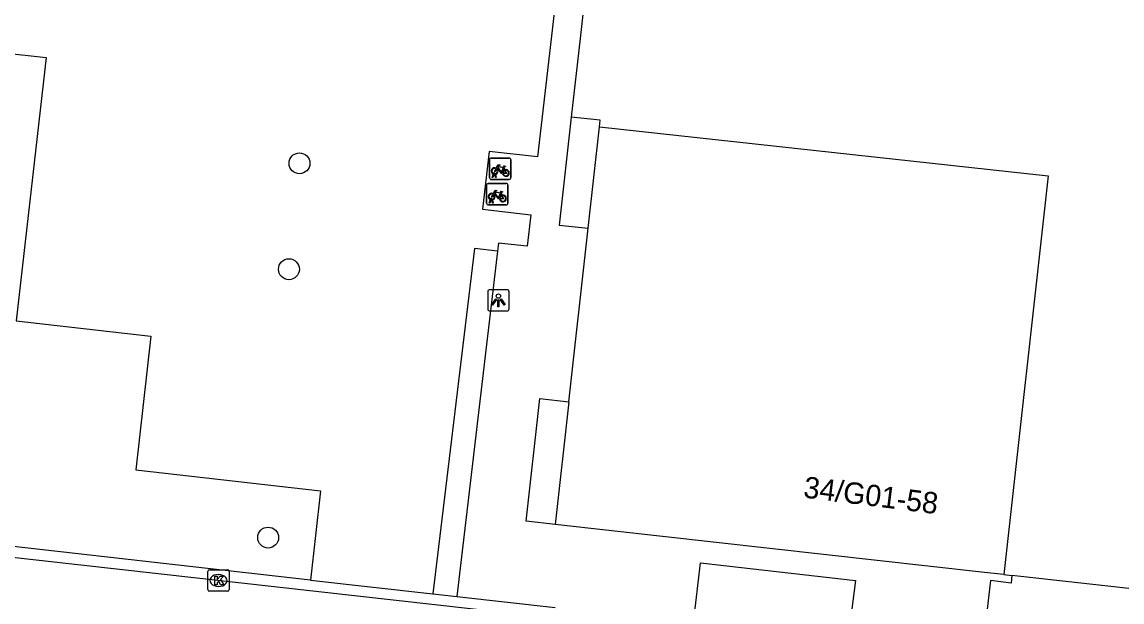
# Model space of a CAD drawing. Extents: x 161928 to 163055, y 386475 to 387428.
# Drawn here: x 162126.5 to 162177.9, y 387093.2 to 387120.3 of the extents above; entities that cross this region are included whole.
import ezdxf

# ---------------------------------------------------------------- set-up
doc = ezdxf.new("R2010")
doc.units = 0
for name, color, linetype in [('IMGEO_Boom', 7, 'Continuous'), ('IMGEO_Fietsenrek', 7, 'Continuous'), ('IMGEO_Groenvoorziening', 7, 'Continuous'), ('IMGEO_Kolk', 7, 'Continuous'), ('IMGEO_Lichtpunt', 7, 'Continuous'), ('IMGEO_Pand', 7, 'Continuous'), ('IMGEO_Pand_nummerreeks', 7, 'Continuous'), ('IMGEO_Rijbaan_lokaal_open', 7, 'Continuous'), ('IMGEO_Voetpad_open', 7, 'Continuous')]:
    doc.layers.add(name, color=color, linetype=linetype)

msp = doc.modelspace()

# ---------------------------------------------------------------- linework, layer by layer
at = {"layer": 'IMGEO_Boom'}
for centre in [(162139.439, 387113.732), (162138.945, 387108.775), (162137.971, 387096.215)]:
    msp.add_circle(centre, 0.489, dxfattribs=at)
at = {"layer": 'IMGEO_Fietsenrek'}
for p, q in [((162148.334, 387113.053), (162148.334, 387113.894)), ((162148.334, 387113.894), (162148.334, 387113.053)), ((162148.409, 387113.978), (162149.25, 387113.978)), ((162149.25, 387113.978), (162148.409, 387113.978)), ((162149.334, 387113.903), (162149.334, 387113.062)), ((162149.334, 387113.062), (162149.334, 387113.903)), ((162148.461, 387113.062), (162148.5, 387113.222)), ((162148.495, 387113.062), (162148.461, 387113.062)), ((162148.53, 387113.21), (162148.495, 387113.062)), ((162148.572, 387113.234), (162148.571, 387113.238)), ((162148.613, 387113.062), (162148.579, 387113.204)), ((162148.603, 387113.245), (162148.604, 387113.238)), ((162148.611, 387113.208), (162148.646, 387113.062)), ((162148.646, 387113.062), (162148.613, 387113.062)), ((162149.021, 387113.527), (162149.057, 387113.432)), ((162148.195, 387111.861), (162148.195, 387112.702)), ((162148.195, 387112.702), (162148.195, 387111.861)), ((162148.27, 387112.786), (162149.111, 387112.786)), ((162149.111, 387112.786), (162148.27, 387112.786)), ((162149.259, 387112.978), (162148.418, 387112.978)), ((162148.418, 387112.978), (162149.259, 387112.978)), ((162149.195, 387112.711), (162149.195, 387111.87)), ((162149.195, 387111.87), (162149.195, 387112.711)), ((162148.322, 387111.87), (162148.361, 387112.03)), ((162148.391, 387112.018), (162148.356, 387111.87)), ((162148.433, 387112.042), (162148.432, 387112.046)), ((162148.474, 387111.87), (162148.44, 387112.012)), ((162148.464, 387112.053), (162148.465, 387112.046)), ((162148.472, 387112.016), (162148.507, 387111.87)), ((162148.882, 387112.335), (162148.918, 387112.24)), ((162149.12, 387111.786), (162148.279, 387111.786)), ((162148.279, 387111.786), (162149.12, 387111.786)), ((162148.356, 387111.87), (162148.322, 387111.87)), ((162148.507, 387111.87), (162148.474, 387111.87))]:
    msp.add_line(p, q, dxfattribs=at)
for points in [[(162148.647, 387113.504), (162148.742, 387113.668), (162148.828, 387113.654), (162148.83, 387113.645), (162148.774, 387113.634), (162148.747, 387113.589), (162149.003, 387113.548)], [(162148.99, 387113.523), (162148.733, 387113.564), (162148.716, 387113.535), (162148.883, 387113.315), (162148.99, 387113.523)], [(162149.003, 387113.548), (162149.028, 387113.597), (162149.022, 387113.601), (162148.999, 387113.605), (162148.987, 387113.612), (162148.986, 387113.615), (162148.988, 387113.62), (162149.083, 387113.605), (162149.085, 387113.595), (162149.075, 387113.582), (162149.063, 387113.576), (162149.049, 387113.582), (162149.021, 387113.527)], [(162148.668, 387113.452), (162148.616, 387113.362), (162148.576, 387113.337), (162148.577, 387113.384), (162148.632, 387113.478)], [(162148.943, 387113.26), (162148.893, 387113.26), (162148.702, 387113.511), (162148.683, 387113.479)], [(162149.038, 387113.425), (162149.008, 387113.502), (162148.899, 387113.284), (162148.942, 387113.284)], [(162148.972, 387113.284), (162149.092, 387113.283), (162149.048, 387113.397)], [(162149.068, 387113.404), (162149.123, 387113.259), (162148.973, 387113.259)], [(162148.529, 387112.26), (162148.477, 387112.17), (162148.437, 387112.145), (162148.438, 387112.192), (162148.493, 387112.286)], [(162148.508, 387112.312), (162148.603, 387112.476), (162148.689, 387112.462), (162148.691, 387112.453), (162148.635, 387112.442), (162148.608, 387112.397), (162148.864, 387112.356)], [(162148.804, 387112.068), (162148.754, 387112.068), (162148.563, 387112.319), (162148.544, 387112.287)], [(162148.851, 387112.331), (162148.594, 387112.372), (162148.577, 387112.343), (162148.744, 387112.123), (162148.851, 387112.331)], [(162148.899, 387112.233), (162148.869, 387112.31), (162148.76, 387112.092), (162148.803, 387112.092)], [(162148.833, 387112.092), (162148.953, 387112.091), (162148.909, 387112.205)], [(162148.929, 387112.212), (162148.984, 387112.067), (162148.834, 387112.067)], [(162148.864, 387112.356), (162148.889, 387112.405), (162148.883, 387112.409), (162148.86, 387112.413), (162148.848, 387112.42), (162148.847, 387112.423), (162148.849, 387112.428), (162148.944, 387112.413), (162148.946, 387112.403), (162148.936, 387112.39), (162148.924, 387112.384), (162148.91, 387112.39), (162148.882, 387112.335)]]:
    msp.add_lwpolyline(points, dxfattribs=at)
for centre, radius, start, end in [((162148.412, 387113.9), 0.0779, 92.4484, 184.2845), ((162148.412, 387113.9), 0.0779, 92.4484, 184.2845), ((162149.256, 387113.9), 0.0779, 2.4484, 94.2845), ((162149.256, 387113.9), 0.0779, 2.4484, 94.2845), ((162148.412, 387113.056), 0.0779, 182.4484, 274.2845), ((162148.412, 387113.056), 0.0779, 182.4484, 274.2845), ((162148.574, 387113.363), 0.159, 62.6766, 242.1369), ((162148.574, 387113.363), 0.129, 63.3192, 238.903), ((162148.554, 387113.234), 0.0499, 12.8025, 158.6934), ((162148.574, 387113.363), 0.159, 253.9967, 271.7867), ((162148.554, 387113.234), 0.0174, 12.8025, 163.4502), ((162148.574, 387113.363), 0.129, 253.415, 269.0204), ((162148.574, 387113.363), 0.129, 283.6043, 43.4302), ((162148.574, 387113.363), 0.159, 283.5766, 46.6042), ((162149.101, 387113.279), 0.159, 113.3408, 178.3217), ((162149.101, 387113.279), 0.159, 187.0065, 105.7708), ((162149.101, 387113.279), 0.129, 113.923, 177.9556), ((162149.101, 387113.279), 0.129, 188.6715, 104.5883), ((162149.256, 387113.056), 0.0779, 272.4484, 4.2845), ((162149.256, 387113.056), 0.0779, 272.4484, 4.2845), ((162148.273, 387112.708), 0.0779, 92.4484, 184.2845), ((162148.273, 387112.708), 0.0779, 92.4484, 184.2845), ((162149.117, 387112.708), 0.0779, 2.4484, 94.2845), ((162149.117, 387112.708), 0.0779, 2.4484, 94.2845), ((162148.435, 387112.171), 0.159, 62.6766, 242.1369), ((162148.435, 387112.171), 0.129, 63.3192, 238.903), ((162148.415, 387112.042), 0.0499, 12.8025, 158.6934), ((162148.435, 387112.171), 0.159, 253.9967, 271.7867), ((162148.415, 387112.042), 0.0174, 12.8025, 163.4502), ((162148.435, 387112.171), 0.129, 253.415, 269.0204), ((162148.435, 387112.171), 0.129, 283.6043, 43.4302), ((162148.435, 387112.171), 0.159, 283.5766, 46.6042), ((162148.962, 387112.087), 0.159, 113.3408, 178.3217), ((162148.962, 387112.087), 0.159, 187.0065, 105.7708), ((162148.962, 387112.087), 0.129, 113.923, 177.9556), ((162148.962, 387112.087), 0.129, 188.6715, 104.5883), ((162148.273, 387111.864), 0.0779, 182.4484, 274.2845), ((162148.273, 387111.864), 0.0779, 182.4484, 274.2845), ((162149.117, 387111.864), 0.0779, 272.4484, 4.2845), ((162149.117, 387111.864), 0.0779, 272.4484, 4.2845)]:
    msp.add_arc(centre, radius, start, end, dxfattribs=at)
at = {"layer": 'IMGEO_Groenvoorziening'}
for points in [[(162154.203, 387127.848), (162155.402, 387137.861), (162174.608, 387135.503), (162173.926, 387129.945), (162180.477, 387129.142), (162179.565, 387121.698), (162182.791, 387121.303), (162181.309, 387109.194), (162185.131, 387108.727), (162184.179, 387100.935), (162179.719, 387101.481), (162178.823, 387093.771), (162172.783, 387094.444)], [(162123.607, 387119.13), (162127.577, 387118.679), (162126.18, 387106.357), (162132.489, 387105.642), (162131.78, 387099.381), (162140.424, 387098.403), (162139.952, 387094.229)], [(162148.715, 387109.615), (162147.632, 387109.743), (162145.679, 387093.582)]]:
    msp.add_lwpolyline(points, dxfattribs=at)
at = {"layer": 'IMGEO_Kolk'}
for p, q in [((162135.149, 387093.78), (162135.149, 387094.632)), ((162135.224, 387094.706), (162136.076, 387094.706)), ((162136.15, 387094.632), (162136.15, 387093.78)), ((162135.637, 387094.486), (162135.662, 387094.486)), ((162136.076, 387093.706), (162135.224, 387093.706)), ((162135.66, 387093.926), (162135.635, 387093.926))]:
    msp.add_line(p, q, dxfattribs=at)
for points in [[(162135.149, 387093.78), (162135.149, 387094.632)], [(162135.224, 387094.706), (162136.076, 387094.706)], [(162136.15, 387094.632), (162136.15, 387093.78)], [(162135.47, 387094.406), (162135.593, 387094.406), (162135.593, 387094.255), (162135.723, 387094.406), (162135.887, 387094.406), (162135.741, 387094.255), (162135.894, 387094.006), (162135.742, 387094.006), (162135.657, 387094.17), (162135.593, 387094.103), (162135.593, 387094.006), (162135.47, 387094.006), (162135.47, 387094.406)], [(162136.076, 387093.706), (162135.224, 387093.706)]]:
    msp.add_lwpolyline(points, dxfattribs=at)
for centre, start, end in [((162135.226, 387094.63), 91.552, 178.448), ((162135.226, 387094.63), 91.552, 178.448), ((162136.074, 387094.63), 1.552, 88.448), ((162136.074, 387094.63), 1.552, 88.448), ((162135.226, 387093.782), 181.552, 268.448), ((162135.226, 387093.782), 181.552, 268.448), ((162136.074, 387093.782), 271.552, 358.448), ((162136.074, 387093.782), 271.552, 358.448)]:
    msp.add_arc(centre, 0.0765, start, end, dxfattribs=at)
for centre, major_axis, ratio, start_param, end_param in [((162135.636, 387094.206), (-0.387, 0.002), 0.722429, 4.712389, 7.853982), ((162135.661, 387094.206), (-0.39, 0.002), 0.717154, 1.570796, 4.712389)]:
    msp.add_ellipse(centre, major_axis=major_axis, ratio=ratio, start_param=start_param, end_param=end_param, dxfattribs=at)
at = {"layer": 'IMGEO_Lichtpunt'}
for p, q in [((162148.253, 387107.722), (162148.253, 387106.915)), ((162148.253, 387107.722), (162148.253, 387106.915)), ((162149.155, 387107.817), (162148.347, 387107.817)), ((162149.155, 387107.817), (162148.347, 387107.817)), ((162149.249, 387106.915), (162149.249, 387107.722)), ((162149.249, 387106.915), (162149.249, 387107.722)), ((162148.347, 387106.821), (162149.155, 387106.821)), ((162148.347, 387106.821), (162149.155, 387106.821))]:
    msp.add_line(p, q, dxfattribs=at)
for points in [[(162148.627, 387107.386), (162148.666, 387107.358), (162148.478, 387107.096), (162148.44, 387107.123), (162148.627, 387107.386)], [(162148.839, 387107.358), (162148.877, 387107.385), (162149.064, 387107.123), (162149.025, 387107.095), (162148.839, 387107.358)], [(162148.729, 387107.338), (162148.776, 387107.338), (162148.776, 387107.016), (162148.729, 387107.016), (162148.729, 387107.338)]]:
    msp.add_lwpolyline(points, dxfattribs=at)
msp.add_circle((162148.752, 387107.52), 0.0994, dxfattribs=at)
for centre, start, end in [((162148.347, 387107.722), 90, 180), ((162148.347, 387107.722), 90, 180), ((162149.155, 387107.722), 0, 90), ((162149.155, 387107.722), 0, 90), ((162148.347, 387106.915), 180, 270), ((162148.347, 387106.915), 180, 270), ((162149.155, 387106.915), 270, 0), ((162149.155, 387106.915), 270, 360)]:
    msp.add_arc(centre, 0.0946, start, end, dxfattribs=at)
at = {"layer": 'IMGEO_Pand'}
for points in [[(162152.957, 387110.691), (162153.486, 387115.447)], [(162153.486, 387115.447), (162174.482, 387113.146), (162172.408, 387094.486)], [(162152.053, 387102.572), (162152.957, 387110.691)], [(162152.053, 387102.572), (162151.413, 387096.826)], [(162172.408, 387094.486), (162171.5, 387094.587), (162151.413, 387096.826)]]:
    msp.add_lwpolyline(points, dxfattribs=at)
at = {"layer": 'IMGEO_Rijbaan_lokaal_open'}
msp.add_lwpolyline([(162151.345, 387092.449), (162123.614, 387095.554), (162121.01, 387095.806)], dxfattribs=at)
at = {"layer": 'IMGEO_Voetpad_open'}
for points in [[(162154.203, 387127.848), (162155.544, 387127.699), (162155.244, 387125.016), (162153.206, 387125.243), (162152.573, 387119.574), (162152.163, 387115.897)], [(162149.642, 387125.907), (162151.927, 387125.641), (162150.578, 387114.029), (162148.324, 387114.291), (162148.01, 387111.589), (162150.265, 387111.327), (162150.094, 387109.847), (162148.761, 387110.002), (162148.715, 387109.615)], [(162152.163, 387115.897), (162151.599, 387110.842), (162152.957, 387110.691)], [(162153.486, 387115.447), (162153.519, 387115.745), (162152.163, 387115.897)], [(162148.715, 387109.615), (162146.808, 387093.454)], [(162151.413, 387096.826), (162150.052, 387096.978), (162150.693, 387102.723), (162152.053, 387102.572)], [(162139.952, 387094.229), (162121.073, 387096.363)], [(162157.876, 387092.22), (162158.203, 387095.04), (162165.471, 387094.213), (162165.113, 387091.434)], [(162139.952, 387094.229), (162145.679, 387093.582)], [(162172.783, 387094.444), (162172.744, 387094.088), (162171.782, 387094.2), (162171.377, 387090.708)], [(162172.408, 387094.486), (162172.783, 387094.444)], [(162145.679, 387093.582), (162146.808, 387093.454)], [(162146.808, 387093.454), (162151.4, 387092.945)]]:
    msp.add_lwpolyline(points, dxfattribs=at)

# ---------------------------------------------------------------- texts
at = {"layer": 'IMGEO_Pand_nummerreeks'}
msp.add_text('34/G01-58', height=1, rotation=352.875, dxfattribs=at).set_placement((162162.994, 387098.094))

doc.saveas('drawing.dxf')
